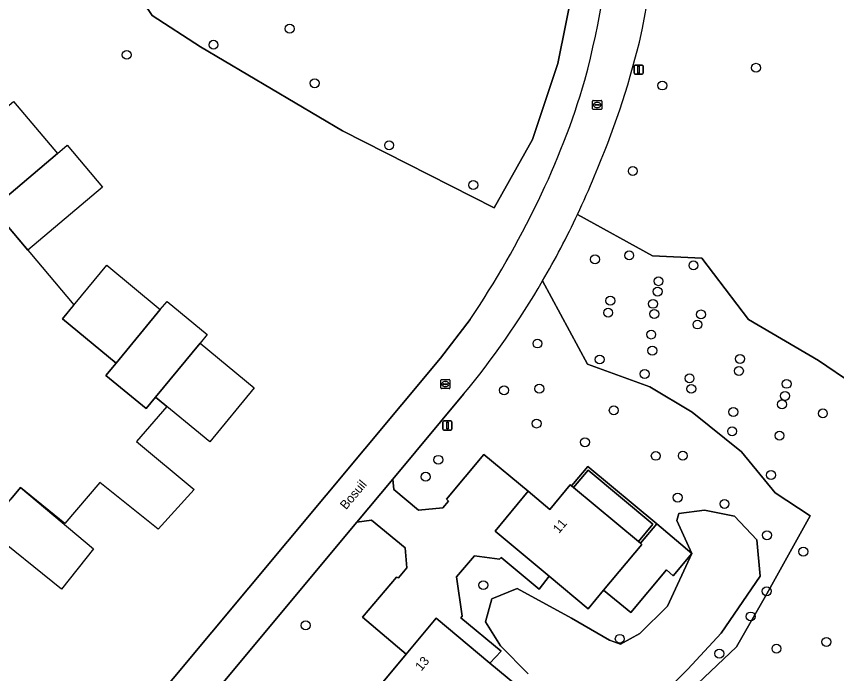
# Model space of a CAD drawing. Extents: x 156661 to 157576, y 383570 to 384425.
# Drawn here: x 156996.3 to 157086.2, y 383808.2 to 383880.2 of the extents above; entities that cross this region are included whole.
import ezdxf

# ---------------------------------------------------------------- set-up
doc = ezdxf.new("R2010")
doc.units = 0
for name, color, linetype in [('IMGEO_Boom', 7, 'Continuous'), ('IMGEO_Erf', 7, 'Continuous'), ('IMGEO_Groenvoorziening', 7, 'Continuous'), ('IMGEO_Lichtmast', 7, 'Continuous'), ('IMGEO_Loofbos', 7, 'Continuous'), ('IMGEO_Meer_plas_ven_vijver', 7, 'Continuous'), ('IMGEO_Muur', 7, 'Continuous'), ('IMGEO_Openbare_ruimte_label', 7, 'Continuous'), ('IMGEO_Pand', 7, 'Continuous'), ('IMGEO_Pand_nummerreeks', 7, 'Continuous'), ('IMGEO_Pand_vergunning_verleend', 7, 'Continuous'), ('IMGEO_Rijbaan_lokaal_open', 7, 'Continuous'), ('IMGEO_Rioolput', 7, 'Continuous')]:
    doc.layers.add(name, color=color, linetype=linetype)

msp = doc.modelspace()

# ---------------------------------------------------------------- linework, layer by layer
at = {"layer": 'IMGEO_Boom'}
for centre in [(157026.208, 383878.882), (157017.862, 383877.124), (157008.356, 383876.019), (157077.331, 383874.599), (157028.953, 383872.902), (157067.058, 383872.653), (157037.114, 383866.097), (157063.824, 383863.275), (157046.332, 383861.741), (157063.427, 383854.027), (157059.682, 383853.591), (157070.474, 383852.929), (157066.64, 383851.198), (157066.537, 383850.064), (157061.36, 383849.06), (157066.037, 383848.714), (157061.122, 383847.746), (157066.173, 383847.608), (157071.291, 383847.554), (157070.911, 383846.45), (157065.837, 383845.351), (157053.373, 383844.367), (157065.958, 383843.589), (157060.197, 383842.614), (157075.578, 383842.68), (157075.45, 383841.358), (157065.124, 383841.032), (157070.04, 383840.546), (157053.572, 383839.415), (157070.229, 383839.399), (157080.678, 383839.943), (157049.713, 383839.24), (157080.51, 383838.624), (157080.178, 383837.693), (157061.738, 383837.037), (157074.836, 383836.865), (157084.655, 383836.701), (157053.276, 383835.592), (157074.711, 383834.739), (157079.903, 383834.264), (157058.578, 383833.544), (157042.512, 383831.616), (157066.341, 383832.051), (157069.305, 383832.066), (157041.114, 383829.758), (157078.977, 383829.95), (157068.738, 383827.476), (157073.874, 383826.78), (157078.531, 383823.344), (157082.508, 383821.547), (157047.439, 383817.871), (157078.498, 383817.207), (157076.749, 383814.441), (157027.968, 383813.468), (157062.395, 383811.991), (157085.044, 383811.651), (157079.572, 383810.912), (157073.312, 383810.365)]:
    msp.add_circle(centre, 0.489, dxfattribs=at)
at = {"layer": 'IMGEO_Erf'}
for points in [[(157052.363, 383828.161), (157047.492, 383832.207), (157043.413, 383827.286), (157043.628, 383827.093), (157043.018, 383826.358), (157040.343, 383826.081), (157037.619, 383828.379), (157037.526, 383829.502), (157033.585, 383824.777), (157035.192, 383825), (157038.856, 383821.957), (157039.059, 383819.784), (157038.154, 383818.673), (157037.917, 383818.762), (157034.179, 383814.379), (157038.979, 383810.3), (157042.256, 383814.242), (157048.157, 383809.325), (157049.383, 383810.642), (157044.984, 383814.308), (157045.135, 383814.489), (157044.499, 383818.776), (157046.472, 383821.101), (157049.207, 383820.705), (157049.379, 383820.893), (157053.545, 383817.442), (157054.659, 383818.851), (157048.722, 383823.791)], [(157058.914, 383830.465), (157057.339, 383828.574), (157064.449, 383822.653), (157066.024, 383824.544)], [(157070.285, 383821.341), (157066.439, 383824.582), (157064.676, 383822.464), (157064.814, 383822.349), (157060.62, 383817.313), (157063.589, 383814.878), (157067.504, 383819.551), (157068.237, 383818.91)]]:
    msp.add_lwpolyline(points, close=True, dxfattribs=at)
at = {"layer": 'IMGEO_Groenvoorziening'}
msp.add_lwpolyline([(157058.511, 383896.433), (157058.506, 383896.82), (157058.418, 383896.745), (157055.904, 383896.289), (157051.303, 383896.382), (157048.983, 383894.367), (157045.629, 383892.859), (157041.142, 383892.89), (157033.089, 383893.802), (157029.876, 383893.975), (157025.097, 383892.911), (157015.681, 383891.686), (157010.865, 383890.715), (157007.751, 383889.615), (157005.669, 383888.491), (157011.144, 383880.337), (157016.422, 383876.906), (157031.991, 383867.671), (157048.615, 383859.226), (157052.837, 383866.747), (157055.608, 383875.059), (157057.323, 383883.635)], close=True, dxfattribs=at)
for points in [[(157016.422, 383876.906), (157011.144, 383880.337), (157005.669, 383888.491), (157002.231, 383886.636), (156999.755, 383888.928), (156999.413, 383889.244), (156998.463, 383889.523), (156994.479, 383890.731), (156988.991, 383893.36), (156986.656, 383893.993), (156983.208, 383893.538), (156975.842, 383894.559), (156965.319, 383894.998)], [(157057.767, 383858.53), (157065.965, 383853.982), (157071.375, 383853.718), (157076.52, 383846.989), (157084.173, 383842.503), (157087.933, 383839.93), (157091.43, 383836.764), (157095.948, 383836.137), (157101.325, 383837.028), (157107.856, 383840.062), (157110.825, 383843.295), (157127.449, 383844.35), (157131.671, 383843.163), (157134.838, 383843.163), (157134.31, 383847.517), (157127.449, 383856.225), (157118.477, 383892.64)], [(157057.323, 383883.635), (157055.608, 383875.059), (157052.837, 383866.747), (157048.615, 383859.226), (157031.991, 383867.671), (157016.422, 383876.906)], [(157001.056, 383748.839), (157031.176, 383759.637), (157044.279, 383764.335), (157041.161, 383774.554), (157044.855, 383780.228), (157050.132, 383782.207), (157052.903, 383789.859), (157057.653, 383792.498), (157067.416, 383803.713), (157075.201, 383811.102), (157078.499, 383816.907), (157083.249, 383825.483), (157079.423, 383827.99), (157075.729, 383832.476), (157070.319, 383836.83), (157065.701, 383839.6), (157058.84, 383842.107), (157053.931, 383851.225)], [(156977.657, 383765.109), (156984.098, 383772.514), (157042.748, 383842.776), (157045.986, 383846.984)], [(157045.278, 383838.796), (157037.526, 383829.502), (157037.619, 383828.379), (157040.343, 383826.081), (157043.018, 383826.358), (157043.628, 383827.093), (157043.413, 383827.286), (157047.492, 383832.207), (157052.363, 383828.161), (157054.728, 383826.181), (157056.974, 383828.878), (157057.112, 383828.763), (157057.327, 383829.021), (157058.876, 383830.881), (157066.439, 383824.582), (157070.285, 383821.341), (157068.65, 383824.952), (157068.881, 383825.732), (157071.684, 383826.104), (157074.953, 383825.424), (157077.404, 383822.844), (157077.765, 383818.859), (157073.495, 383812.613), (157069.849, 383808.66), (157067.156, 383805.908)], [(157036.281, 383807.055), (157038.979, 383810.3), (157034.179, 383814.379), (157037.917, 383818.762), (157038.154, 383818.673), (157039.059, 383819.784), (157038.856, 383821.957), (157035.192, 383825), (157033.585, 383824.777), (157011.25, 383798.001)], [(157052.364, 383808.162), (157049.338, 383811.217), (157047.66, 383813.862), (157048.353, 383816.367), (157051.142, 383817.501), (157057.114, 383814.264), (157061.257, 383811.84), (157062.469, 383811.391), (157064.588, 383812.565), (157067.622, 383815.58), (157070.285, 383821.341), (157068.237, 383818.91), (157067.504, 383819.551), (157063.589, 383814.878), (157060.62, 383817.313), (157058.937, 383815.292), (157054.659, 383818.851), (157053.545, 383817.442), (157049.379, 383820.893), (157049.207, 383820.705), (157046.472, 383821.101), (157044.499, 383818.776), (157045.135, 383814.489), (157044.984, 383814.308), (157049.383, 383810.642), (157048.157, 383809.325), (157052.782, 383805.471)]]:
    msp.add_lwpolyline(points, dxfattribs=at)
for centre, radius, start, end in [((156982.068, 383895.793), 84.501, 347.43743, 2.46247), ((156950.957, 383901.264), 111.207, 345.40632, 355.63959), ((156972.596, 383900.104), 94.708, 336.76686, 346.13843), ((156974.33, 383898.202), 87.866, 334.20054, 343.49799), ((156971.36, 383899.123), 95.467, 334.83614, 337.60018), ((156955.826, 383907.386), 108.524, 326.18011, 334.08697), ((156973.101, 383898.272), 93.525, 320.51056, 329.7986)]:
    msp.add_arc(centre, radius, start, end, dxfattribs=at)
at = {"layer": 'IMGEO_Lichtmast'}
for p, q in [((157063.962, 383873.996), (157063.962, 383874.796)), ((157063.962, 383874.796), (157063.962, 383873.996)), ((157064.062, 383874.896), (157064.852, 383874.896)), ((157064.852, 383874.896), (157064.062, 383874.896)), ((157064.952, 383874.796), (157064.952, 383873.996)), ((157064.952, 383873.996), (157064.952, 383874.796)), ((157064.852, 383873.896), (157064.062, 383873.896)), ((157064.062, 383873.896), (157064.852, 383873.896)), ((157043.002, 383834.974), (157043.002, 383835.774)), ((157043.002, 383835.774), (157043.002, 383834.974)), ((157043.102, 383835.874), (157043.892, 383835.874)), ((157043.892, 383835.874), (157043.102, 383835.874)), ((157043.992, 383835.774), (157043.992, 383834.974)), ((157043.992, 383834.974), (157043.992, 383835.774)), ((157043.892, 383834.874), (157043.102, 383834.874)), ((157043.102, 383834.874), (157043.892, 383834.874))]:
    msp.add_line(p, q, dxfattribs=at)
for points in [[(157064.382, 383874.771), (157064.532, 383874.771), (157064.532, 383874.021), (157064.382, 383874.021), (157064.382, 383874.771)], [(157043.422, 383835.749), (157043.572, 383835.749), (157043.572, 383834.999), (157043.422, 383834.999), (157043.422, 383835.749)]]:
    msp.add_lwpolyline(points, dxfattribs=at)
for centre, start, end in [((157064.062, 383874.796), 90, 180), ((157064.062, 383874.796), 90, 180), ((157064.852, 383874.796), 0, 90), ((157064.852, 383874.796), 360, 90), ((157064.062, 383873.996), 180, 270), ((157064.062, 383873.996), 180, 270), ((157064.852, 383873.996), 270, 0), ((157064.852, 383873.996), 270, 0), ((157043.102, 383835.774), 90, 180), ((157043.102, 383835.774), 90, 180), ((157043.892, 383835.774), 0, 90), ((157043.892, 383835.774), 360, 90), ((157043.102, 383834.974), 180, 270), ((157043.102, 383834.974), 180, 270), ((157043.892, 383834.974), 270, 0), ((157043.892, 383834.974), 270, 0)]:
    msp.add_arc(centre, 0.1, start, end, dxfattribs=at)
at = {"layer": 'IMGEO_Loofbos'}
for points in [[(157118.477, 383892.64), (157127.449, 383856.225), (157134.31, 383847.517), (157134.838, 383843.163), (157131.671, 383843.163), (157127.449, 383844.35), (157110.825, 383843.295), (157107.856, 383840.062), (157101.325, 383837.028), (157095.948, 383836.137), (157091.43, 383836.764), (157087.933, 383839.93), (157084.173, 383842.503), (157076.52, 383846.989), (157071.375, 383853.718), (157065.965, 383853.982), (157057.767, 383858.53)], [(157053.931, 383851.225), (157058.84, 383842.107), (157065.701, 383839.6), (157070.319, 383836.83), (157075.729, 383832.476), (157079.423, 383827.99), (157083.249, 383825.483), (157078.499, 383816.907), (157075.201, 383811.102), (157067.416, 383803.713), (157057.653, 383792.498), (157052.903, 383789.859), (157050.132, 383782.207), (157044.855, 383780.228), (157041.161, 383774.554), (157044.279, 383764.335), (157055.927, 383768.511), (157056.08, 383771.905), (157067.612, 383781.99), (157100.642, 383794.067), (157104.049, 383785.763), (157100.533, 383804.768)]]:
    msp.add_lwpolyline(points, dxfattribs=at)
msp.add_arc((156973.093, 383898.334), 93.563, 329.76798, 334.82232, dxfattribs=at)
at = {"layer": 'IMGEO_Meer_plas_ven_vijver'}
for points in [[(157073.495, 383812.613), (157077.765, 383818.859), (157077.404, 383822.844), (157074.953, 383825.424), (157071.684, 383826.104), (157068.881, 383825.732), (157068.65, 383824.952), (157070.285, 383821.341), (157067.622, 383815.58), (157064.588, 383812.565), (157062.469, 383811.391), (157061.257, 383811.84), (157057.114, 383814.264), (157051.142, 383817.501), (157048.353, 383816.367), (157047.66, 383813.862), (157049.338, 383811.217), (157052.364, 383808.162)], [(157035.789, 383768.247), (157040.328, 383778.097), (157044.191, 383784.604), (157048.793, 383787.718), (157058.8, 383796.028), (157064.689, 383801.724), (157067.156, 383805.908), (157069.849, 383808.66), (157073.495, 383812.613)]]:
    msp.add_lwpolyline(points, dxfattribs=at)
at = {"layer": 'IMGEO_Muur'}
msp.add_lwpolyline([(157057.112, 383828.763), (157057.339, 383828.574), (157058.914, 383830.465), (157066.024, 383824.544), (157064.449, 383822.653), (157064.676, 383822.464), (157066.439, 383824.582), (157058.876, 383830.881), (157057.327, 383829.021)], close=True, dxfattribs=at)
at = {"layer": 'IMGEO_Pand'}
for points in [[(157057.339, 383828.574), (157057.112, 383828.763), (157056.974, 383828.878), (157054.728, 383826.181), (157052.363, 383828.161), (157048.722, 383823.791), (157054.659, 383818.851), (157058.937, 383815.292), (157060.62, 383817.313), (157064.814, 383822.349), (157064.676, 383822.464), (157064.449, 383822.653)], [(157052.782, 383805.471), (157048.157, 383809.325), (157042.256, 383814.242), (157038.979, 383810.3), (157036.281, 383807.055), (157036.412, 383806.947), (157036.639, 383806.758), (157046.433, 383798.607), (157046.66, 383798.418), (157046.791, 383798.309), (157049.612, 383801.681)]]:
    msp.add_lwpolyline(points, close=True, dxfattribs=at)
at = {"layer": 'IMGEO_Pand_vergunning_verleend'}
for points in [[(156992.872, 383862.727), (156990.245, 383866.105), (156995.946, 383870.914), (157000.756, 383865.213), (156994.954, 383860.259)], [(156994.954, 383860.259), (157000.756, 383865.213), (157001.809, 383866.101), (157005.687, 383861.505), (156997.495, 383854.594), (156993.647, 383859.156)], [(157012.035, 383848.089), (157007.18, 383842.212), (157001.302, 383847.067), (157006.157, 383852.945)], [(157007.18, 383842.212), (157012.035, 383848.089), (157012.771, 383848.98), (157017.18, 383845.339), (157016.404, 383844.4), (157011.512, 383838.48), (157010.477, 383837.228), (157006.07, 383840.868)], [(157011.512, 383838.48), (157016.404, 383844.4), (157022.335, 383839.5), (157017.444, 383833.579)], [(156993.013, 383824.004), (156995.66, 383827.31), (156996.721, 383828.573), (157004.725, 383821.844), (157001.202, 383817.429)]]:
    msp.add_lwpolyline(points, close=True, dxfattribs=at)
msp.add_lwpolyline([(156993.647, 383859.156), (157002.552, 383848.599), (157001.302, 383847.067), (157007.18, 383842.212), (157006.07, 383840.868), (157010.477, 383837.228), (157011.512, 383838.48), (157012.764, 383837.445), (157009.415, 383833.623), (157015.742, 383828.347), (157011.804, 383823.995), (157005.41, 383829.116), (157001.552, 383824.651), (156996.721, 383828.573), (156995.66, 383827.31)], dxfattribs=at)
at = {"layer": 'IMGEO_Rijbaan_lokaal_open'}
for points in [[(157045.986, 383846.984), (157042.748, 383842.776), (156984.098, 383772.514), (156977.657, 383765.109)], [(156980.924, 383761.917), (156988.102, 383770.249), (157006.477, 383792.278), (157011.25, 383798.001), (157033.585, 383824.777), (157037.526, 383829.502), (157045.278, 383838.796)]]:
    msp.add_lwpolyline(points, dxfattribs=at)
for centre, radius, start, end in [((156982.068, 383895.793), 84.501, 347.43743, 2.46247), ((156950.957, 383901.264), 111.207, 345.40632, 355.63959), ((156972.596, 383900.104), 94.708, 336.76686, 346.13843), ((156974.33, 383898.202), 87.866, 334.20054, 343.49799), ((156971.36, 383899.123), 95.467, 334.83614, 337.60018), ((156955.826, 383907.386), 108.524, 326.18011, 334.08697), ((156973.093, 383898.334), 93.563, 329.76798, 334.82232), ((156973.101, 383898.272), 93.525, 320.51056, 329.7986)]:
    msp.add_arc(centre, radius, start, end, dxfattribs=at)
at = {"layer": 'IMGEO_Rioolput'}
for p, q in [((157059.418, 383870.099), (157059.418, 383870.951)), ((157059.493, 383871.025), (157060.345, 383871.025)), ((157059.677, 383870.519), (157059.677, 383870.531)), ((157060.115, 383870.482), (157059.717, 383870.482)), ((157059.72, 383870.568), (157060.118, 383870.568)), ((157059.906, 383870.805), (157059.931, 383870.805)), ((157060.161, 383870.531), (157060.161, 383870.519)), ((157060.419, 383870.951), (157060.419, 383870.099)), ((157060.345, 383870.025), (157059.493, 383870.025)), ((157059.929, 383870.245), (157059.904, 383870.245)), ((157042.778, 383839.492), (157042.778, 383840.344)), ((157042.853, 383840.418), (157043.705, 383840.418)), ((157043.037, 383839.912), (157043.037, 383839.924)), ((157043.475, 383839.875), (157043.077, 383839.875)), ((157043.08, 383839.961), (157043.478, 383839.961)), ((157043.266, 383840.198), (157043.291, 383840.198)), ((157043.521, 383839.924), (157043.521, 383839.912)), ((157043.779, 383840.344), (157043.779, 383839.492)), ((157043.705, 383839.418), (157042.853, 383839.418)), ((157043.289, 383839.638), (157043.264, 383839.638))]:
    msp.add_line(p, q, dxfattribs=at)
for points in [[(157059.418, 383870.099), (157059.418, 383870.951)], [(157059.493, 383871.025), (157060.345, 383871.025)], [(157060.419, 383870.951), (157060.419, 383870.099)], [(157060.345, 383870.025), (157059.493, 383870.025)], [(157042.778, 383839.492), (157042.778, 383840.344)], [(157042.853, 383840.418), (157043.705, 383840.418)], [(157043.779, 383840.344), (157043.779, 383839.492)], [(157043.705, 383839.418), (157042.853, 383839.418)]]:
    msp.add_lwpolyline(points, dxfattribs=at)
for centre, radius, start, end in [((157059.495, 383870.949), 0.0765, 91.55205, 178.44795), ((157059.495, 383870.949), 0.0765, 91.55205, 178.44795), ((157059.717, 383870.528), 0.0403, 85.87752, 175.75265), ((157059.714, 383870.518), 0.0366, 178.93798, 274.71019), ((157060.118, 383870.525), 0.043, 264.86636, 352.45326), ((157060.122, 383870.53), 0.0386, 1.73085, 96.63898), ((157060.343, 383870.949), 0.0765, 1.55205, 88.44795), ((157060.343, 383870.949), 0.0765, 1.55205, 88.44795), ((157059.495, 383870.101), 0.0765, 181.55205, 268.44795), ((157059.495, 383870.101), 0.0765, 181.55205, 268.44795), ((157060.343, 383870.101), 0.0765, 271.55205, 358.44795), ((157060.343, 383870.101), 0.0765, 271.55205, 358.44795), ((157042.855, 383840.342), 0.0765, 91.55205, 178.44795), ((157042.855, 383840.342), 0.0765, 91.55205, 178.44795), ((157043.077, 383839.921), 0.0403, 85.87752, 175.75265), ((157043.074, 383839.911), 0.0366, 178.93798, 274.71019), ((157043.478, 383839.918), 0.043, 264.86636, 352.45326), ((157043.482, 383839.923), 0.0386, 1.73085, 96.63898), ((157043.703, 383840.342), 0.0765, 1.55205, 88.44795), ((157043.703, 383840.342), 0.0765, 1.55205, 88.44795), ((157042.855, 383839.494), 0.0765, 181.55205, 268.44795), ((157042.855, 383839.494), 0.0765, 181.55205, 268.44795), ((157043.703, 383839.494), 0.0765, 271.55205, 358.44795), ((157043.703, 383839.494), 0.0765, 271.55205, 358.44795)]:
    msp.add_arc(centre, radius, start, end, dxfattribs=at)
for centre, major_axis, ratio, start_param, end_param in [((157059.905, 383870.525), (-0.387, 0.002), 0.722429, 4.712389, 7.853982), ((157059.93, 383870.525), (-0.39, 0.002), 0.717154, 1.570796, 4.712389), ((157043.265, 383839.918), (-0.387, 0.002), 0.722429, 4.712389, 7.853982), ((157043.29, 383839.918), (-0.39, 0.002), 0.717154, 1.570796, 4.712389)]:
    msp.add_ellipse(centre, major_axis=major_axis, ratio=ratio, start_param=start_param, end_param=end_param, dxfattribs=at)

# ---------------------------------------------------------------- texts
at = {"layer": 'IMGEO_Openbare_ruimte_label'}
msp.add_text('Bosuil', height=1, rotation=50.19443, dxfattribs=at).set_placement((157032.398, 383826.083))
at = {"layer": 'IMGEO_Pand_nummerreeks'}
for s, rotation, p in [('11', 50.21402, (157055.726, 383823.472)), ('13', 50.25986, (157040.638, 383808.386))]:
    msp.add_text(s, height=1, rotation=rotation, dxfattribs=at).set_placement(p)

doc.saveas('drawing.dxf')
